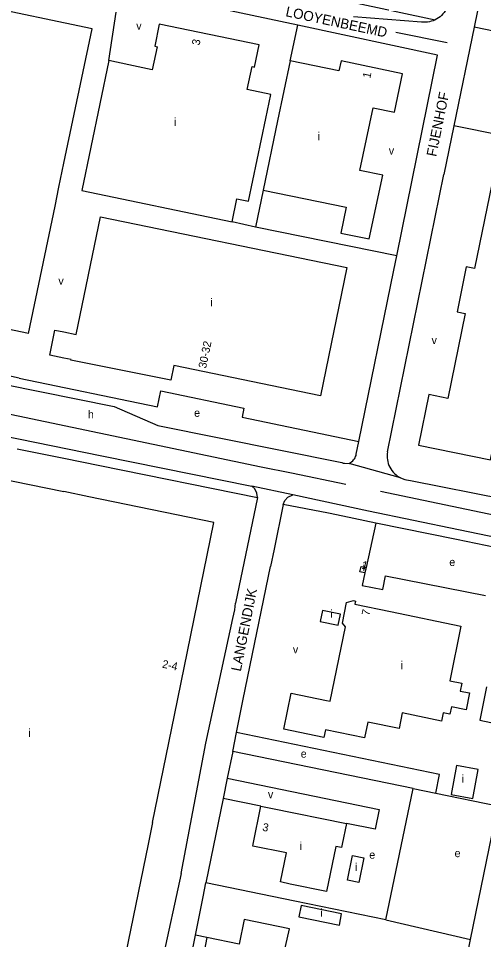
# Model space of a CAD drawing. Extents: x 157699 to 159683, y 381451 to 383293.
# Drawn here: x 158027.2 to 158260, y 381952.4 to 382412.9 of the extents above; entities that cross this region are included whole.
import ezdxf

# ---------------------------------------------------------------- set-up
doc = ezdxf.new("R2010")
doc.units = 0
for name, color, linetype in [('BLT_Basislijn', 7, 'Continuous'), ('BLT_Bebouwing', 7, 'Continuous'), ('BLT_Centroide', 7, 'Continuous'), ('BLT_Huisnummer', 7, 'Continuous'), ('BLT_Huisnummer_reeks', 7, 'Continuous'), ('BLT_Straatnaam', 7, 'Continuous'), ('BLT_Vlakafsluiter', 7, 'Continuous')]:
    doc.layers.add(name, color=color, linetype=linetype)

msp = doc.modelspace()

# ---------------------------------------------------------------- linework, layer by layer
at = {"layer": 'BLT_Basislijn'}
for p, q in [((158167.06, 382409.46), (158078.71, 382428.33)), ((158194.34, 382420.96), (158235.68, 382412.15)), ((158072.5, 382391.84), (158076.17, 382415.97)), ((158228.89, 382411.03), (158194.81, 382413.76)), ((158163.15, 382391.72), (158167.06, 382409.46)), ((158215.99, 382406.09), (158241.79, 382400.78)), ((158255.23, 382408.53), (158245.09, 382359.23)), ((158306.25, 382397.75), (158255.23, 382408.53)), ((158245.09, 382359.23), (158240.07, 382334.82)), ((158269.05, 382354.34), (158245.09, 382359.23)), ((158211.83, 382196.24), (158240.07, 382334.82)), ((158149.68, 382327.09), (158145.86, 382308.58)), ((158145.86, 382308.58), (158134.13, 382311.19)), ((158197.54, 382201.35), (158215.02, 382286.97)), ((158196.25, 382195.06), (158197.54, 382201.35)), ((158026.58, 382197.69), (158050, 382192.97)), ((158163.94, 382185.79), (158191.1, 382180.12)), ((158223.44, 382181.91), (158339.58, 382158.81)), ((158206.12, 382160.61), (158189.51, 382164.02)), ((158206.12, 382160.61), (158201.17, 382138.42)), ((158246.44, 382152.33), (158206.12, 382160.61)), ((158292.26, 382142.92), (158246.44, 382152.33)), ((158155.13, 382147.55), (158153.34, 382138.9)), ((158139.74, 382072.6), (158153.34, 382138.9)), ((158121.03, 382050.49), (158134.54, 382112.93)), ((158136.37, 382055.81), (158139.74, 382072.6)), ((158134.46, 382046.32), (158136.37, 382055.81)), ((158108.6, 381985.35), (158121.03, 382050.49)), ((158134.46, 382046.32), (158131.74, 382033.03)), ((158224.69, 382027.86), (158134.46, 382046.32)), ((158131.74, 382033.03), (158129.67, 382022.93)), ((158211.07, 381962.18), (158224.69, 382027.86)), ((158224.69, 382027.86), (158236.05, 382025.53)), ((158129.67, 382022.93), (158121.02, 381980.65)), ((158148.57, 382019.07), (158129.67, 382022.93)), ((158236.05, 382025.53), (158266.85, 382019.2)), ((158108.6, 381985.35), (158092.48, 381911.08)), ((158211.07, 381962.18), (158253.39, 381952.43)), ((158121.53, 381953.4), (158115.79, 381954.57))]:
    msp.add_line(p, q, dxfattribs=at)
for points in [[(158271.37, 382484.25), (158264.83, 382455.22), (158255.23, 382408.53)], [(158242.07, 382419.4), (158241.72, 382418.47), (158241.3, 382417.57), (158240.8, 382416.71), (158240.24, 382415.89), (158239.61, 382415.12), (158238.93, 382414.4), (158238.18, 382413.74), (158237.39, 382413.14), (158236.55, 382412.61), (158235.68, 382412.15)], [(158235.68, 382412.15), (158234.76, 382411.76), (158233.82, 382411.44), (158232.86, 382411.2), (158231.88, 382411.04), (158230.89, 382410.95), (158229.89, 382410.95), (158228.89, 382411.03)], [(158216.5, 382294.21), (158236.99, 382394.53), (158167.06, 382409.46)], [(158216.5, 382294.21), (158145.86, 382308.58)], [(158215.02, 382286.97), (158216.5, 382294.21)], [(158027.64, 382233.05), (157935.82, 382252.96)], [(157935.97, 382247.63), (157946.89, 382244.69), (158075.13, 382218.86), (158097.02, 382209.33), (158189.06, 382190.81)], [(157912.82, 382235.37), (157919.74, 382233.13), (157927.13, 382231.2), (157992.2, 382218.03), (158013.48, 382217.01), (158148.74, 382188.63), (158163.94, 382185.79)], [(158027.64, 382233.05), (158096.89, 382218.64), (158098.55, 382226.62), (158140.08, 382217.98), (158139.15, 382213.5), (158197.54, 382201.35)], [(157987.46, 382210.67), (158027.23, 382202.65)], [(158027.23, 382202.65), (158068.98, 382194.24), (158143.99, 382179.11)], [(158192.79, 382190.37), (158194.5, 382191.69), (158194.96, 382192.15), (158195.36, 382192.65), (158195.69, 382193.21), (158195.95, 382193.8), (158196.14, 382194.41), (158196.25, 382195.06)], [(158211.83, 382196.24), (158211.71, 382195.25), (158211.67, 382194.26), (158211.7, 382193.27), (158211.82, 382192.28), (158212.01, 382191.31), (158212.29, 382190.36), (158212.63, 382189.43), (158213.06, 382188.53), (158213.55, 382187.67), (158214.11, 382186.85), (158214.74, 382186.08), (158215.42, 382185.36), (158216.16, 382184.7), (158216.95, 382184.1), (158218.34, 382183.13)], [(158050, 382192.97), (158067.99, 382189.34)], [(158067.99, 382189.34), (158146.88, 382173.43)], [(158189.06, 382190.81), (158189.67, 382190.6), (158190.3, 382190.47), (158192.79, 382190.37)], [(158218.34, 382183.13), (158220.52, 382182.4), (158221.48, 382182.16), (158222.46, 382181.99), (158223.44, 382181.91)], [(158146.88, 382173.43), (158146.59, 382175.59), (158145.58, 382177.64), (158143.99, 382179.11)], [(158208.33, 382176.62), (158362.08, 382144.32), (158412.5, 382136.57), (158505.73, 382117.34)], [(158146.88, 382173.43), (158135.84, 382120.48)], [(158159.75, 382169.81), (158160.47, 382171.87), (158162, 382173.59), (158164.6, 382174.65)], [(158247.44, 382157.23), (158202.34, 382166.49), (158164.6, 382174.65)], [(158159.75, 382169.81), (158155.13, 382147.55)], [(158189.51, 382164.02), (158182.45, 382165.47), (158159.75, 382169.81)], [(158407.75, 382124.15), (158374.23, 382131.09), (158247.44, 382157.23)], [(158200.59, 382135.68), (158199.19, 382129.38), (158209.54, 382127.4), (158210.85, 382134.13), (158260.84, 382124.37)], [(158134.54, 382112.93), (158135.51, 382117.2), (158135.84, 382120.48)], [(158236.05, 382025.53), (158237.98, 382034.93), (158136.37, 382055.81)], [(158131.74, 382033.03), (158207.74, 382017.38), (158205.73, 382007.53), (158191.3, 382010.4)], [(158115.79, 381954.57), (158119.66, 381973.73), (158121.02, 381980.65)], [(158211.07, 381962.18), (158165.52, 381971.55), (158121.02, 381980.65)], [(158111.75, 381934.53), (158115.79, 381954.57)]]:
    msp.add_lwpolyline(points, dxfattribs=at)
at = {"layer": 'BLT_Bebouwing'}
for p, q in [((158150.96, 382362.87), (158153.45, 382374.85)), ((158142.37, 382321.46), (158150.96, 382362.87)), ((158032.2, 382255.36), (158045.54, 382319.04)), ((158062.5, 382173.74), (158050, 382176.3)), ((158183.26, 382071.55), (158190.86, 382108.71)), ((158094.36, 382010.89), (158105.31, 382064.51)), ((158253.39, 381952.43), (158265.37, 382010.94)), ((158245.23, 381912.56), (158253.39, 381952.43))]:
    msp.add_line(p, q, dxfattribs=at)
for points in [[(158064.19, 382407.61), (158006.84, 382419.65), (157988.31, 382331.62), (157933.9, 382343.05)], [(158147.64, 382399.66), (158097.72, 382410.07), (158095.42, 382398.96), (158096.6, 382398.7), (158094.2, 382387.27), (158082.45, 382389.68), (158072.5, 382391.84)], [(158050, 382340.49), (158064.19, 382407.61)], [(158153.45, 382374.85), (158141.76, 382377.34), (158144.12, 382388.78), (158145.32, 382388.54), (158147.64, 382399.66)], [(158072.5, 382391.84), (158058.96, 382326.9)], [(158163.15, 382391.72), (158156.87, 382361.61)], [(158219.39, 382385.18), (158188.66, 382391.66), (158187.59, 382386.61), (158163.15, 382391.72)], [(158202.8, 382302.66), (158209.52, 382334.52), (158198.09, 382336.93), (158204.69, 382368.21), (158215.34, 382365.96), (158219.39, 382385.18)], [(158156.87, 382361.61), (158149.68, 382327.09)], [(158269.05, 382354.34), (158255.36, 382287.79), (158251.26, 382288.64), (158246.7, 382266.18), (158250.79, 382265.4), (158242.04, 382222.93), (158232.57, 382224.87), (158227.38, 382199.6), (158263.48, 382192.17), (158265.31, 382201.04), (158338.58, 382185.98)], [(158047.52, 382328.59), (158050, 382340.49)], [(158045.54, 382319.04), (158047.52, 382328.59)], [(158058.96, 382326.9), (158134.13, 382311.19)], [(158149.68, 382327.09), (158191.29, 382318.49), (158188.6, 382305.6), (158202.8, 382302.66)], [(158134.13, 382311.19), (158136.53, 382322.68), (158142.37, 382321.46)], [(158050, 382256.14), (158056.12, 382254.86), (158068.35, 382313.75), (158191.55, 382288.32), (158178.3, 382224.18), (158105, 382239.32), (158103.5, 382231.98), (158053.51, 382242.03), (158053.56, 382242.29), (158050, 382243.03)], [(158032.2, 382255.36), (157955.86, 382271.39)], [(158050, 382243.03), (158042.93, 382244.5), (158045.53, 382257.07), (158050, 382256.14)], [(157997.38, 382187.07), (158000, 382186.53), (158050, 382176.3)], [(158105.31, 382064.51), (158125.01, 382160.95), (158062.5, 382173.74)], [(158200.59, 382135.68), (158198.13, 382136.19), (158198.72, 382138.95), (158201.17, 382138.42)], [(158201.17, 382138.42), (158200.59, 382135.68)], [(158190.86, 382108.71), (158189.3, 382110.47), (158191.45, 382120.85)], [(158191.45, 382120.85), (158194.9, 382121.8), (158195.95, 382121.59), (158195.62, 382119.98), (158213.34, 382116.35)], [(158213.34, 382116.35), (158248.61, 382109.12), (158243.06, 382081.79), (158249.11, 382080.54), (158248.3, 382076.62), (158253, 382075.66), (158251.24, 382067.14), (158243.89, 382068.65), (158243.15, 382065.05), (158239.78, 382065.74), (158238.92, 382061.61), (158219.31, 382065.65), (158217.66, 382057.87), (158202.03, 382061.09), (158200.39, 382053.27), (158180.83, 382057.26), (158180.01, 382053.37), (158160.09, 382057.47), (158163.73, 382075.49), (158181.39, 382071.93), (158183.26, 382071.55)], [(158261.47, 382078.79), (158258.03, 382062.03), (158271.5, 382059.27)], [(158191.3, 382010.4), (158189.17, 382000), (158188.83, 381998.36), (158186.01, 381998.94), (158181.37, 381976.4), (158163.25, 381980.14), (158158.35, 381981.15), (158161.32, 381995.69), (158144.49, 381999.13), (158144.67, 382000), (158148.57, 382019.07)], [(158148.57, 382019.07), (158153.47, 382018.08), (158191.3, 382010.4)], [(158094.36, 382010.89), (158092.13, 381999.99), (158079.65, 381939.18)], [(158197.6, 381980.87), (158191.87, 381982.05), (158194.4, 381994.37), (158200.13, 381993.19), (158197.6, 381980.87)], [(158155.92, 381925.46), (158159.22, 381941.61), (158162.78, 381957.8), (158140.23, 381962.43), (158137.74, 381950.1), (158121.53, 381953.4)], [(158121.53, 381953.4), (158119.92, 381945.56), (158117.43, 381933.3)]]:
    msp.add_lwpolyline(points, dxfattribs=at)
for points in [[(158188.31, 382115.11), (158179.3, 382116.95), (158178.13, 382111.32), (158187.14, 382109.48)], [(158246.34, 382039.4), (158243.74, 382024.88), (158254.63, 382022.94), (158257.23, 382037.46)], [(158168.78, 381969.38), (158167.61, 381963.75), (158187.8, 381959.57), (158188.96, 381965.2)]]:
    msp.add_lwpolyline(points, close=True, dxfattribs=at)
at = {"layer": 'BLT_Vlakafsluiter'}
for p, q in [((158218.34, 382183.13), (158192.79, 382190.37)), ((158164.6, 382174.65), (158143.99, 382179.11))]:
    msp.add_line(p, q, dxfattribs=at)

# ---------------------------------------------------------------- texts
at = {"layer": 'BLT_Centroide'}
for s, p in [('v', (158086.19, 382407.22)), ('i', (158105, 382359.16)), ('i', (158176.89, 382352)), ('v', (158212.54, 382344.83)), ('v', (158047.23, 382279.73)), ('i', (158123.3, 382268.97)), ('v', (158233.95, 382250.07)), ('h', (158062, 382212.92)), ('e', (158115.13, 382213.73)), ('i', (158199.49, 382136.7)), ('e', (158242.8, 382139.11)), ('i', (158183.22, 382113.22)), ('v', (158164.55, 382095.44)), ('i', (158218.51, 382087.53)), ('i', (158032.22, 382053.7)), ('e', (158168.47, 382043.3)), ('i', (158249.04, 382030.79)), ('v', (158152.09, 382023.04)), ('i', (158167.91, 381997.17)), ('e', (158202.76, 381992.78)), ('e', (158245.45, 381993.57)), ('i', (158195.57, 381986.66)), ('i', (158178.34, 381963.8))]:
    msp.add_text(s, height=4, dxfattribs=at).set_placement(p)
at = {"layer": 'BLT_Huisnummer'}
for s, rotation, p in [('3', 79.0112, (158117.84, 382399.21)), ('1', 78.0927, (158203.26, 382382.74)), ('1', 348.5336, (158198.74, 382137.84)), ('7', 78.5336, (158202.81, 382114.09)), ('3', 348.4597, (158149.07, 382006.82))]:
    msp.add_text(s, height=4, rotation=rotation, dxfattribs=at).set_placement(p)
at = {"layer": 'BLT_Huisnummer_reeks'}
for s, rotation, p in [('30-32', 78.3878, (158121.11, 382237.72)), ('2-4', 348.5057, (158098.88, 382088.35))]:
    msp.add_text(s, height=4, rotation=rotation, dxfattribs=at).set_placement(p)
at = {"layer": 'BLT_Straatnaam'}
for s, height, rotation, p in [('LOOYENBEEMD', 4.9999, 347.9979, (158160.62, 382414.06)), ('FIJENHOF', 5, 78.4682, (158236.24, 382343.51)), ('LANGENDIJK', 5, 78.8091, (158138.49, 382086.16))]:
    msp.add_text(s, height=height, rotation=rotation, dxfattribs=at).set_placement(p)

doc.saveas('drawing.dxf')
